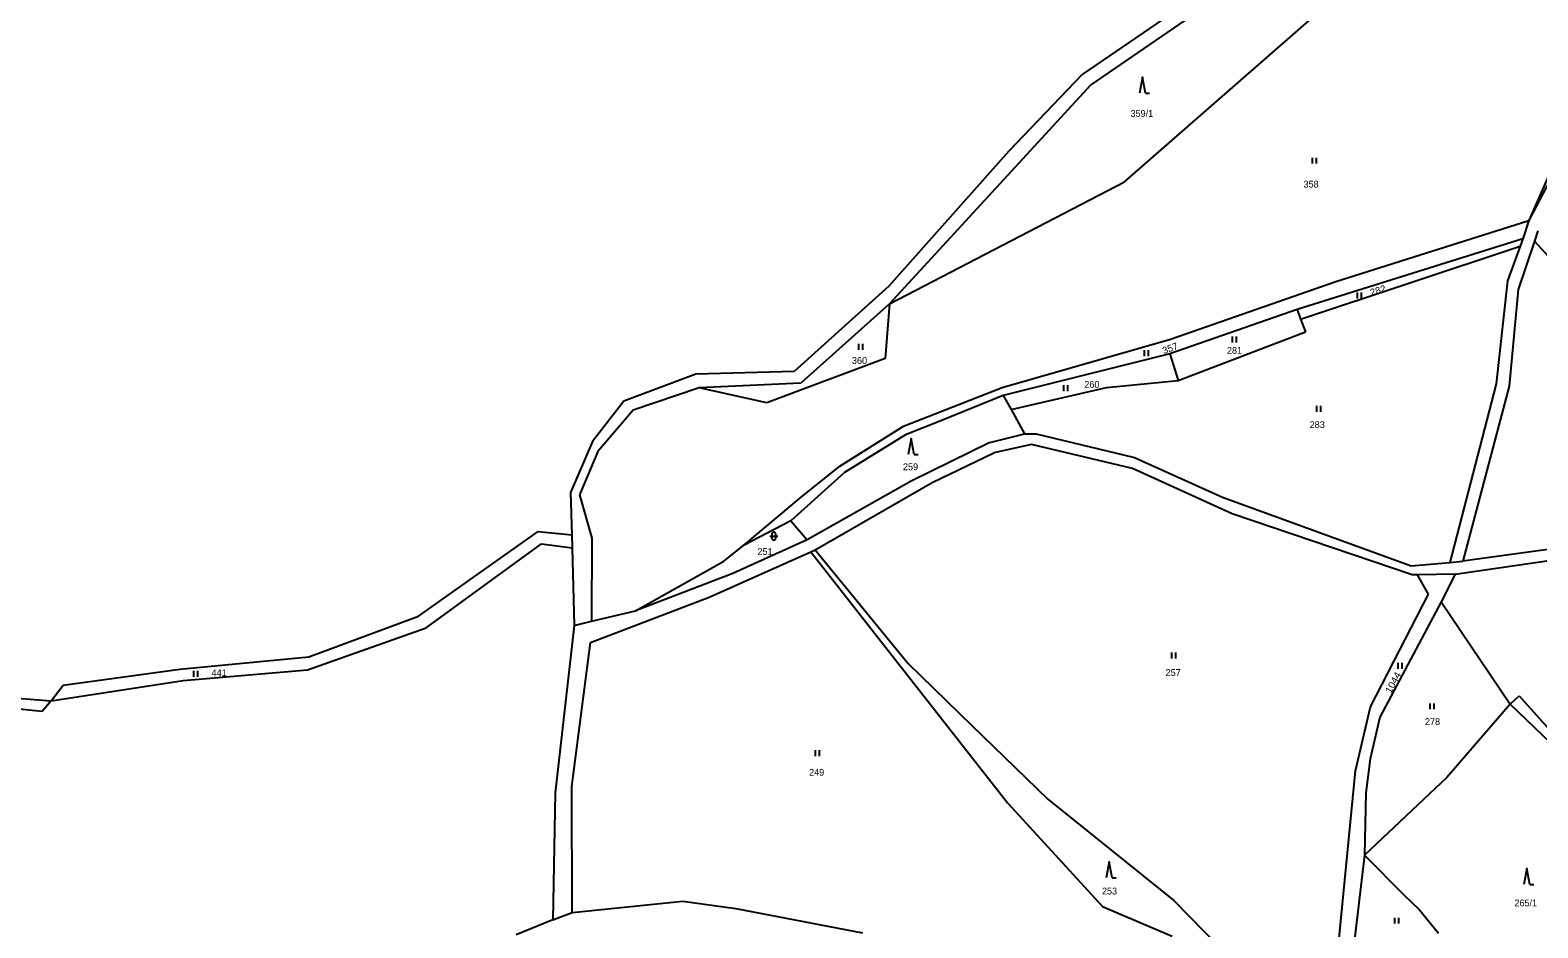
# Model space of a CAD drawing. Extents: x -744132 to -742433, y -984679 to -982287.
# Drawn here: x -743418.3 to -743040.9, y -983932.1 to -983707.4 of the extents above; entities that cross this region are included whole.
import ezdxf

# ---------------------------------------------------------------- set-up
doc = ezdxf.new("R2010")
doc.units = 0
doc.header["$LTSCALE"] = 0.68
doc.layers.add('1', color=7, linetype='Continuous', lineweight=25)
doc.layers.add('3', color=7, linetype='Continuous', lineweight=25)
doc.layers.add('2', color=7, linetype='Continuous')

msp = doc.modelspace()

# ---------------------------------------------------------------- linework, layer by layer
at = {"layer": '1'}
for p, q in [((-743095.85, -983678.02), (-743155, -983718.55)), ((-743104.75, -983688.16), (-743152.82, -983721.07)), ((-743144.38, -983745.38), (-743094.86, -983702.13)), ((-743155, -983718.55), (-743173.31, -983737.73)), ((-743152.82, -983721.07), (-743203.23, -983775.94)), ((-743030.51, -983726.19), (-743043.12, -983755.07)), ((-743028.24, -983726.47), (-743043.12, -983755.07)), ((-743173.31, -983737.73), (-743203.4, -983771.51)), ((-743203.23, -983775.94), (-743144.38, -983745.38)), ((-743091.47, -983770.35), (-743043.12, -983755.07)), ((-743043.12, -983755.07), (-743044.69, -983759.61)), ((-743040.87, -983757.6), (-743041.78, -983760.21)), ((-743044.69, -983759.61), (-743101.17, -983777.31)), ((-743100.28, -983779.71), (-743045.36, -983761.49)), ((-743045.36, -983761.49), (-743048.46, -983770.16)), ((-743041.78, -983760.21), (-743045.8, -983772.34)), ((-743044.69, -983759.61), (-743045.36, -983761.49)), ((-743041.78, -983760.21), (-743031.68, -983771.34)), ((-743203.4, -983771.51), (-743227.06, -983792.84)), ((-743132.86, -983784.75), (-743091.47, -983770.35)), ((-743048.46, -983770.16), (-743051.32, -983795.92)), ((-743045.8, -983772.34), (-743048.12, -983796.48)), ((-743203.23, -983775.94), (-743225.43, -983795.76)), ((-743203.23, -983775.94), (-743204.31, -983789.6)), ((-743101.17, -983777.31), (-743132.99, -983788.43)), ((-743101.17, -983777.31), (-743100.28, -983779.71)), ((-743100.28, -983779.71), (-743099.03, -983782.89)), ((-743174.97, -983796.82), (-743132.86, -983784.75)), ((-743130.98, -983795.07), (-743099.03, -983782.89)), ((-743132.99, -983788.43), (-743157.4, -983794.48)), ((-743132.99, -983788.43), (-743130.98, -983795.07)), ((-743204.31, -983789.6), (-743233.87, -983800.67)), ((-743251.67, -983793.55), (-743269.73, -983800.3)), ((-743227.06, -983792.84), (-743251.67, -983793.55)), ((-743225.43, -983795.76), (-743250.82, -983796.97)), ((-743157.4, -983794.48), (-743174.79, -983798.85)), ((-743148.85, -983796.81), (-743130.98, -983795.07)), ((-743051.32, -983795.92), (-743062.91, -983840.63)), ((-743250.82, -983796.97), (-743267.35, -983802.49)), ((-743233.87, -983800.67), (-743250.82, -983796.97)), ((-743199.74, -983806.52), (-743174.97, -983796.82)), ((-743174.79, -983798.85), (-743190.37, -983805.19)), ((-743174.79, -983798.85), (-743172.74, -983802.32)), ((-743172.74, -983802.32), (-743148.85, -983796.81)), ((-743048.12, -983796.48), (-743059.72, -983840.28)), ((-743269.73, -983800.3), (-743277.57, -983810.33)), ((-743267.35, -983802.49), (-743276.19, -983812.86)), ((-743172.74, -983802.32), (-743169.4, -983808.43)), ((-743215.62, -983816.53), (-743199.74, -983806.52)), ((-743190.37, -983805.19), (-743199.21, -983808.67)), ((-743277.57, -983810.33), (-743283.03, -983823.09)), ((-743199.21, -983808.67), (-743214.47, -983818.13)), ((-743178.11, -983810.63), (-743197.81, -983820.32)), ((-743178.11, -983810.63), (-743169.4, -983808.43)), ((-743167.68, -983811.13), (-743177.12, -983813.23)), ((-743169.4, -983808.43), (-743166.52, -983808.45)), ((-743142.38, -983817.12), (-743167.68, -983811.13)), ((-743166.52, -983808.45), (-743141.85, -983814.34)), ((-743276.19, -983812.86), (-743280.8, -983823.74)), ((-743192.53, -983820.61), (-743177.12, -983813.23)), ((-743141.85, -983814.34), (-743119.87, -983824.28)), ((-743214.47, -983818.13), (-743227.9, -983830.22)), ((-743225.28, -983824.28), (-743215.62, -983816.53)), ((-743117.4, -983828.5), (-743142.38, -983817.12)), ((-743197.81, -983820.32), (-743223.83, -983834.99)), ((-743221.79, -983837.48), (-743192.53, -983820.61)), ((-743283.03, -983823.09), (-743282.76, -983833.72)), ((-743280.8, -983823.74), (-743277.73, -983834.53)), ((-743239.79, -983836.35), (-743225.28, -983824.28)), ((-743119.87, -983824.28), (-743072.64, -983841.45)), ((-743227.9, -983830.22), (-743239.79, -983836.35)), ((-743227.9, -983830.22), (-743223.83, -983834.99)), ((-743072.34, -983843.7), (-743117.4, -983828.5)), ((-743321.08, -983854.1), (-743291.16, -983832.89)), ((-743291.16, -983832.89), (-743282.76, -983833.72)), ((-743282.76, -983833.72), (-743282.68, -983836.99)), ((-743319.17, -983856.96), (-743290.32, -983835.96)), ((-743290.32, -983835.96), (-743282.68, -983836.99)), ((-743282.68, -983836.99), (-743282.18, -983856.42)), ((-743277.73, -983834.53), (-743277.84, -983855.33)), ((-743244.7, -983840.3), (-743239.79, -983836.35)), ((-743223.83, -983834.99), (-743242.45, -983843.41)), ((-743222.91, -983837.98), (-743221.79, -983837.48)), ((-743221.79, -983837.48), (-743198.49, -983865.92)), ((-743022.73, -983835.22), (-743059.72, -983840.28)), ((-743266.77, -983852.76), (-743244.7, -983840.3)), ((-743248.36, -983849.28), (-743222.91, -983837.98)), ((-743222.91, -983837.98), (-743173.57, -983900.91)), ((-743072.64, -983841.45), (-743062.91, -983840.63)), ((-743062.91, -983840.63), (-743059.72, -983840.28)), ((-743061.62, -983843.55), (-743023.06, -983837.99)), ((-743242.45, -983843.41), (-743266.77, -983852.76)), ((-743071.04, -983843.7), (-743072.34, -983843.7)), ((-743061.62, -983843.55), (-743071.04, -983843.7)), ((-743068.25, -983848.54), (-743071.04, -983843.7)), ((-743061.62, -983843.55), (-743065.07, -983850.5)), ((-743082.76, -983876.8), (-743068.25, -983848.54)), ((-743278.09, -983860.67), (-743248.36, -983849.28)), ((-743277.84, -983855.33), (-743266.77, -983852.76)), ((-743065.07, -983850.5), (-743080.45, -983879.33)), ((-743065.07, -983850.5), (-743047.81, -983876.13)), ((-743348.54, -983864.23), (-743321.08, -983854.1)), ((-743282.18, -983856.42), (-743286.91, -983898.32)), ((-743282.18, -983856.42), (-743277.84, -983855.33)), ((-743348.87, -983867.5), (-743319.17, -983856.96)), ((-743380.83, -983867.3), (-743348.54, -983864.23)), ((-743282.75, -983896.69), (-743278.09, -983860.67)), ((-743410.02, -983871.35), (-743380.83, -983867.3)), ((-743379.99, -983870.14), (-743348.87, -983867.5)), ((-743198.49, -983865.92), (-743182.61, -983881.4)), ((-743413.04, -983875.25), (-743379.99, -983870.14)), ((-743413.04, -983875.25), (-743410.02, -983871.35)), ((-743450.34, -983872.31), (-743413.04, -983875.25)), ((-743415.34, -983877.96), (-743449.87, -983874.5)), ((-743413.04, -983875.25), (-743415.34, -983877.96)), ((-743047.81, -983876.13), (-743045.62, -983873.99)), ((-743045.62, -983873.99), (-743035.53, -983885.15)), ((-743086.56, -983892.78), (-743082.76, -983876.8)), ((-743080.45, -983879.33), (-743082.9, -983889.8)), ((-743047.81, -983876.13), (-743063.72, -983894.45)), ((-743047.81, -983876.13), (-743035.84, -983887.63)), ((-743182.61, -983881.4), (-743163.53, -983899.89)), ((-743082.9, -983889.8), (-743083.93, -983898.32)), ((-743091.56, -983943.76), (-743086.56, -983892.78)), ((-743063.72, -983894.45), (-743084.28, -983913.88)), ((-743282.64, -983928.27), (-743282.75, -983896.69)), ((-743286.91, -983898.32), (-743287.49, -983930.07)), ((-743163.53, -983899.89), (-743132, -983925.25)), ((-743083.93, -983898.32), (-743084.28, -983913.88)), ((-743084.28, -983913.88), (-743087.79, -983943.69)), ((-743084.28, -983913.88), (-743074.46, -983923.8)), ((-743074.46, -983923.8), (-743070.49, -983927.58)), ((-743287.49, -983930.07), (-743282.64, -983928.27)), ((-743282.64, -983928.27), (-743254.92, -983925.4)), ((-743254.92, -983925.4), (-743241.66, -983927.21)), ((-743241.66, -983927.21), (-743209.97, -983933.36)), ((-743132, -983925.25), (-743112.96, -983944.67)), ((-743070.49, -983927.58), (-743065.79, -983933.41)), ((-743287.49, -983930.07), (-743296.65, -983933.81))]:
    msp.add_line(p, q, dxfattribs=at)
msp.add_lwpolyline([(-743173.57, -983900.91), (-743149.9, -983926.7), (-743132.41, -983934.14)], dxfattribs=at)
at = {"layer": '3'}
for p, q in [((-743139.12, -983723.21), (-743138.124, -983723.21)), ((-743097.301, -983740.83), (-743097.301, -983739.33)), ((-743096.3, -983740.83), (-743096.3, -983739.33)), ((-743086.091, -983774.54), (-743086.091, -983773.04)), ((-743085.09, -983774.54), (-743085.09, -983773.04)), ((-743117.331, -983785.58), (-743117.331, -983784.08)), ((-743116.33, -983785.58), (-743116.33, -983784.08)), ((-743210.861, -983787.43), (-743210.861, -983785.93)), ((-743209.86, -983787.43), (-743209.86, -983785.93)), ((-743139.381, -983788.97), (-743139.381, -983787.47)), ((-743138.38, -983788.97), (-743138.38, -983787.47)), ((-743159.561, -983797.74), (-743159.561, -983796.24)), ((-743158.56, -983797.74), (-743158.56, -983796.24)), ((-743096.261, -983802.91), (-743096.261, -983801.41)), ((-743095.26, -983802.91), (-743095.26, -983801.41)), ((-743197.05, -983813.59), (-743196.054, -983813.59)), ((-743233.171, -983834.051), (-743231.169, -983834.051)), ((-743232.671, -983833.551), (-743232.671, -983834.552)), ((-743231.669, -983834.552), (-743231.669, -983833.551)), ((-743132.511, -983864.68), (-743132.511, -983863.18)), ((-743131.51, -983864.68), (-743131.51, -983863.18)), ((-743377.311, -983869.22), (-743377.311, -983867.72)), ((-743376.31, -983869.22), (-743376.31, -983867.72)), ((-743075.861, -983867.24), (-743075.861, -983865.74)), ((-743074.86, -983867.24), (-743074.86, -983865.74)), ((-743067.821, -983877.39), (-743067.821, -983875.89)), ((-743066.82, -983877.39), (-743066.82, -983875.89)), ((-743221.761, -983889.12), (-743221.761, -983887.62)), ((-743220.76, -983889.12), (-743220.76, -983887.62)), ((-743147.48, -983919.59), (-743146.484, -983919.59)), ((-743042.88, -983921.2), (-743041.884, -983921.2)), ((-743076.681, -983931.03), (-743076.681, -983929.53)), ((-743075.68, -983931.03), (-743075.68, -983929.53))]:
    msp.add_line(p, q, dxfattribs=at)
for points in [[(-743139.12, -983723.21), (-743139.87, -983719.21), (-743140.62, -983723.21)], [(-743197.05, -983813.59), (-743197.8, -983809.59), (-743198.55, -983813.59)], [(-743147.48, -983919.59), (-743148.23, -983915.59), (-743148.98, -983919.59)], [(-743042.88, -983921.2), (-743043.63, -983917.2), (-743044.38, -983921.2)]]:
    msp.add_lwpolyline(points, dxfattribs=at)
for centre, start, end in [((-743232.17, -983833.5509), 0, 180), ((-743232.17, -983834.5509), 180, 359.98789)]:
    msp.add_arc(centre, 0.5, start, end, dxfattribs=at)

# ---------------------------------------------------------------- texts
at = {"layer": '2'}
for s, p in [('359/1', (-743142.87, -983729.115)), ('358', (-743099.57, -983746.815)), ('281', (-743118.73, -983788.415)), ('360', (-743212.61, -983790.945)), ('260', (-743154.44, -983796.925)), ('283', (-743098.03, -983807.005)), ('259', (-743199.84, -983817.545)), ('251', (-743236.26, -983838.755)), ('441', (-743372.91, -983869.095)), ('257', (-743134.09, -983869.035)), ('278', (-743069.17, -983881.315)), ('249', (-743223.34, -983893.995)), ('253', (-743150.03, -983923.725)), ('265/1', (-743046.78, -983926.695))]:
    msp.add_text(s, height=1.7, dxfattribs=at).set_placement(p)
for s, rotation, width, p in [('282', 17, 1.05, (-743082.585, -983773.936)), ('357', 20, 1.05, (-743134.544, -983788.499)), ('1044', 62, 1.1, (-743077.694, -983873.539))]:
    msp.add_text(s, height=1.7, rotation=rotation, dxfattribs=dict(at, width=width)).set_placement(p)

doc.saveas('drawing.dxf')
